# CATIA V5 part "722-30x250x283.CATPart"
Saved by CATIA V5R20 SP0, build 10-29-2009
Part number: 722-30x250x283
Definition: NONE
Nomenclature: 722-30x250x283
Source: Unknown
Description: 722-30x250x283
Bounding box of the stored display mesh (mm): x -15 to 15, y -15 to 15, z -235 to 48
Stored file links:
  C:\Users\Utente\Desktop\IO LAVORO\3D X SITO CF\X SITO\722\722-30x250x283.CATPart
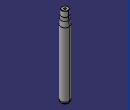
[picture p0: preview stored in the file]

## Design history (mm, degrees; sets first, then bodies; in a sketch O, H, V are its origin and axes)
Body1 "722-30x250x283" (main body)
  Solid1: solid without history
